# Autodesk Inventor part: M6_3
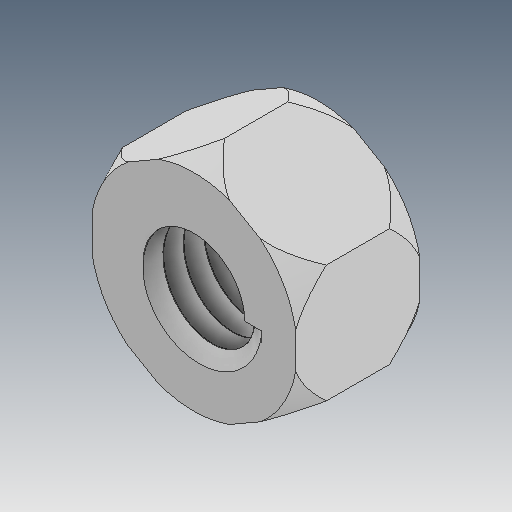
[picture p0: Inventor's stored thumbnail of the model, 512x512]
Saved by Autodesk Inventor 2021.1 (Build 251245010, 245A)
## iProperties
Created: 2019-04
Part Number: M6_3
Material: Ogólny
Document SubType Name: Modeling
Designer: user
Density: 1 g/cm^3
Appearance: Domyślna
Author: user
Revision Number: ÈÎºÎ
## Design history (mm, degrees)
feature "ÊäÈë1"
node "Bryła1"
